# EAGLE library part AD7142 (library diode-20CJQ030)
Analog Devices AD7142 Programmable Capacitance-to-Digital Converter with Environmental Compensation Description: The AD7142 and AD7142-1 are integrated capacitance-to-digital converters (CDCs) with on-chip environmental calibration for use in systems requiring a novel user input method. The AD7142 and AD7142-1 can interface to external capacitance sensors implementing functions such as capacitive buttons, scroll bars, or joypads. The CDC has 14 inputs, channeled through a switch matrix to a 16-bit, 240 kHz sigma-delta capacitance-to-digital converter. The CDC is capable of sensing changes in the capacitance of the external sensors and uses this information to register a sensor activation. The external sensors can be arranged as a series of buttons, as a scroll bar or wheel, or as a combination of sensor types. By programming the registers, the user has full control over the CDC setup. High resolution scroll bar sensors require software to run on the host processor. The AD7142 and AD7142-1 have on-chip calibration logic to account for changes in the ambient environment. The calibration sequence is performed automatically and at continuous intervals, while the sensors are not touched. This ensures that there are no false or nonregistering touches on the external sensors due to a changing environment. The AD7142 has an SPI-compatible serial interface, and the AD7142-1 has an I2C-compatible serial interface. Both versions of AD7142 have an interrupt output, as well as a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
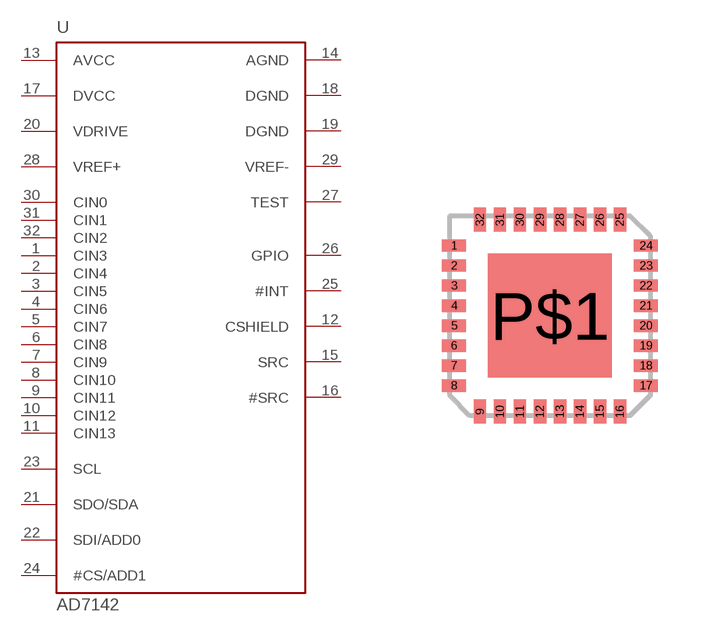
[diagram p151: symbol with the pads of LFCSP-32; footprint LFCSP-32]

Designator prefix U

## AD7142  [LFCSP-32]
1  CIN3  in
2  CIN4  in
3  CIN5  in
4  CIN6  in
5  CIN7  in
6  CIN8  in
7  CIN9  in
8  CIN10  in
9  CIN11  in
10  CIN12  in
11  CIN13  in
12  CSHIELD  out
13  AVCC  pwr
14  AGND  pwr
15  SRC  out
16  #SRC  out
17  DVCC  pwr
18  DGND  pwr
19  DGND  pwr
20  VDRIVE  pwr
21  SDO/SDA
22  SDI/ADD0  in
23  SCL  in
24  #CS/ADD1  in
25  #INT  out
26  GPIO
27  TEST
28  VREF+
29  VREF-
30  CIN0  in
31  CIN1  in
32  CIN2  in

## Footprint LFCSP-32 (pad centres in mm)
Analog Device's 32-Lead Frame Chip Scale Package [LFCSP_VQ] 5 mm × 5 mm Very Thin Quad (CP-32-3)
smd 0.6 x 0.3: 1 -2.4,1.75; 2 -2.4,1.25; 3 -2.4,0.75; 4 -2.4,0.25; 5 -2.4,-0.25; 6 -2.4,-0.75; 7 -2.4,-1.25; 8 -2.4,-1.75; 17 2.4,-1.75; 18 2.4,-1.25; 19 2.4,-0.75; 20 2.4,-0.25; 21 2.4,0.25; 22 2.4,0.75; 23 2.4,1.25; 24 2.4,1.75
smd 0.3 x 0.6: 9 -1.75,-2.4; 10 -1.25,-2.4; 11 -0.75,-2.4; 12 -0.25,-2.4; 13 0.25,-2.4; 14 0.75,-2.4; 15 1.25,-2.4; 16 1.75,-2.4; 25 1.75,2.4; 26 1.25,2.4; 27 0.75,2.4; 28 0.25,2.4; 29 -0.25,2.4; 30 -0.75,2.4; 31 -1.25,2.4; 32 -1.75,2.4
smd 3.1 x 3.1: P$1 0,0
